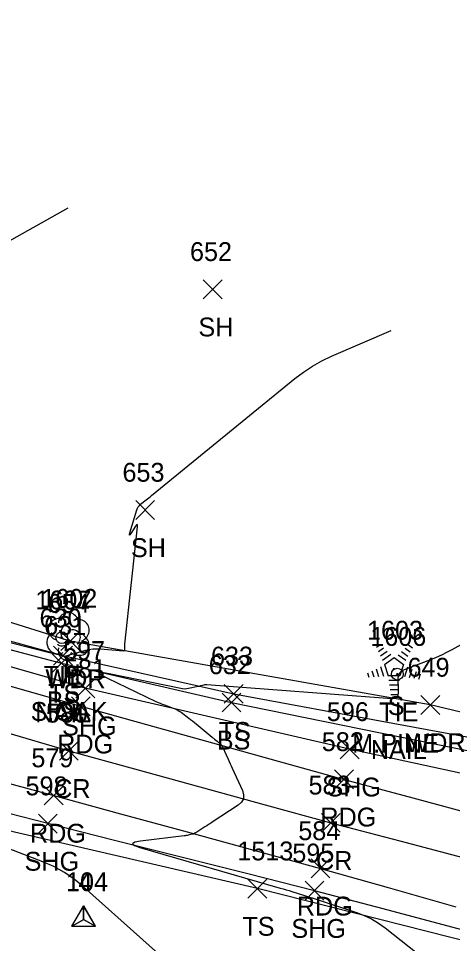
# Model space of a CAD drawing. Extents: x 1592612 to 1596497, y 111838 to 113741.
# Drawn here: x 1593074.6 to 1593120.8, y 113362.1 to 113460.3 of the extents above; entities that cross this region are included whole.
import ezdxf

# ---------------------------------------------------------------- set-up
doc = ezdxf.new("R2010")
doc.units = 0
for name, color, linetype in [('C_A', 7, 'Continuous'), ('C_C', 7, 'Continuous'), ('C_I', 7, 'Continuous'), ('CBP', 7, 'Continuous'), ('CPSM', 7, 'Continuous'), ('L_A', 7, 'Continuous'), ('L_C', 7, 'Continuous'), ('L_I', 7, 'Continuous'), ('L_TIC', 7, 'Continuous'), ('LAWA', 7, 'Continuous'), ('LELB', 7, 'Continuous'), ('LSOGCMA', 7, 'Continuous'), ('LSOGCMI', 7, 'Continuous'), ('LTC', 7, 'Continuous'), ('LTD', 7, 'Continuous'), ('P_A', 7, 'Continuous'), ('P_I', 7, 'Continuous'), ('P_TIC', 7, 'Continuous'), ('PEU', 7, 'Continuous'), ('PRC', 7, 'Continuous'), ('PSU', 7, 'Continuous')]:
    doc.layers.add(name, color=color, linetype=linetype)

msp = doc.modelspace()

# ---------------------------------------------------------------- linework, layer by layer
at = {"layer": 'CBP'}
for centre, radius in [((1593079.238, 113394.544), 0.625), ((1593079.238, 113394.544), 0.0833), ((1593114.889, 113390.674), 0.625), ((1593114.889, 113390.674), 0.0833)]:
    msp.add_circle(centre, radius, dxfattribs=at)
at = {"layer": 'CPSM'}
for p, q in [((1593080.313, 113363.916), (1593081.563, 113366.081)), ((1593080.322, 113363.912), (1593081.572, 113366.077)), ((1593082.813, 113363.916), (1593081.563, 113366.081)), ((1593081.563, 113364.637), (1593081.563, 113366.081)), ((1593082.822, 113363.912), (1593081.572, 113366.077)), ((1593081.572, 113364.633), (1593081.572, 113366.077)), ((1593080.313, 113363.916), (1593081.563, 113364.637)), ((1593080.322, 113363.912), (1593081.572, 113364.633)), ((1593081.563, 113364.637), (1593081.563, 113364.637)), ((1593081.563, 113364.637), (1593082.813, 113363.916)), ((1593081.572, 113364.633), (1593081.572, 113364.633)), ((1593081.572, 113364.633), (1593082.822, 113363.912)), ((1593080.313, 113363.916), (1593082.813, 113363.916)), ((1593080.322, 113363.912), (1593082.822, 113363.912))]:
    msp.add_line(p, q, dxfattribs=at)
at = {"layer": 'L_TIC'}
for points in [[(1593094.27, 113430.519), (1593096.27, 113432.519)], [(1593096.27, 113430.519), (1593094.27, 113432.519)], [(1593087.097, 113407.098), (1593089.097, 113409.098)], [(1593089.097, 113407.098), (1593087.097, 113409.098)], [(1593079.143, 113393.184), (1593081.143, 113395.184)], [(1593081.143, 113393.184), (1593079.143, 113395.184)], [(1593078.367, 113391.639), (1593080.367, 113393.639)], [(1593080.367, 113391.639), (1593078.367, 113393.639)], [(1593078.204, 113390.835), (1593080.204, 113392.835)], [(1593080.204, 113390.835), (1593078.204, 113392.835)], [(1593096.503, 113387.59), (1593098.503, 113389.59)], [(1593098.503, 113387.59), (1593096.503, 113389.59)], [(1593096.266, 113386.672), (1593098.266, 113388.672)], [(1593098.266, 113386.672), (1593096.266, 113388.672)], [(1593117.398, 113386.407), (1593119.398, 113388.407)], [(1593119.398, 113386.407), (1593117.398, 113388.407)], [(1593099.017, 113366.909), (1593101.017, 113368.909)], [(1593101.017, 113366.909), (1593099.017, 113368.909)]]:
    msp.add_lwpolyline(points, dxfattribs=at)
at = {"layer": 'LAWA'}
msp.add_lwpolyline([(1593169.611, 113375.165), (1593118.398, 113387.407), (1593080.143, 113394.184), (1593050.562, 113403.447), (1593019.72, 113413.06), (1592995.657, 113420.841), (1592970.681, 113431.184), (1592941.873, 113445.585), (1592917.884, 113456.286)], dxfattribs=at)
at = {"layer": 'LELB'}
for points in [[(1592908.46, 113460.258), (1592922.596, 113449.566), (1592933.267, 113441.549), (1592945.1, 113436.529), (1592970.28, 113425.515), (1592997.076, 113416.402), (1593023.641, 113407.833), (1593049.418, 113399.686), (1593079.204, 113391.835), (1593097.266, 113387.672), (1593130.658, 113380.878), (1593168.554, 113372.43)], [(1592945.373, 113437.303), (1592970.416, 113426.096), (1592997.179, 113416.812), (1593023.772, 113408.406), (1593049.589, 113400.837), (1593079.367, 113392.638), (1593097.503, 113388.59), (1593131.295, 113382.361), (1593169.279, 113374.833)], [(1593157.216, 113351.758), (1593128.266, 113360.771), (1593100.017, 113367.909), (1593070.216, 113374.835), (1593038.268, 113383.437), (1593013.967, 113383.154), (1593000.038, 113371.416), (1592985.819, 113350.727), (1592975.861, 113332.672)]]:
    msp.add_lwpolyline(points, dxfattribs=at)
at = {"layer": 'LSOGCMA'}
for points in [[(1593055.426, 113398.668), (1593078.233, 113392.909), (1593078.346, 113392.881), (1593078.459, 113392.852), (1593078.572, 113392.824), (1593078.685, 113392.796), (1593079.324, 113392.638), (1593079.344, 113392.633), (1593079.365, 113392.628), (1593079.385, 113392.623), (1593079.406, 113392.619), (1593079.524, 113392.594), (1593079.53, 113392.594), (1593079.535, 113392.594), (1593079.55, 113392.598), (1593079.555, 113392.599), (1593081.787, 113393.21), (1593082.161, 113393.295), (1593082.539, 113393.348), (1593082.92, 113393.368), (1593083.304, 113393.355), (1593085.814, 113393.165), (1593085.874, 113393.169), (1593085.916, 113393.192), (1593085.94, 113393.233), (1593085.947, 113393.292), (1593085.939, 113393.566), (1593085.938, 113393.635), (1593085.939, 113393.703), (1593085.943, 113393.771), (1593085.949, 113393.84), (1593087.285, 113406.304), (1593087.291, 113406.481), (1593087.259, 113406.552), (1593087.189, 113406.517), (1593087.082, 113406.376), (1593086.578, 113405.601), (1593086.476, 113405.459), (1593086.423, 113405.42), (1593086.418, 113405.486), (1593086.461, 113405.655), (1593087.214, 113408.122), (1593087.279, 113408.291), (1593087.368, 113408.444), (1593087.48, 113408.582), (1593087.614, 113408.703), (1593088.199, 113409.158), (1593088.345, 113409.272), (1593088.49, 113409.387), (1593088.634, 113409.503), (1593088.778, 113409.62), (1593104.007, 113422.044), (1593104.921, 113422.739), (1593105.875, 113423.366), (1593106.871, 113423.925), (1593107.908, 113424.416), (1593114.252, 113427.161)], [(1593094.835, 113356.265), (1593081.553, 113368.117), (1593080.562, 113368.925), (1593079.51, 113369.635), (1593078.399, 113370.247), (1593077.227, 113370.76), (1593071.605, 113372.928)]]:
    msp.add_lwpolyline(points, dxfattribs=at)
at = {"layer": 'LSOGCMI'}
for points in [[(1593079.878, 113440.116), (1593065.591, 113432.12)], [(1593128.624, 113397.688), (1593120.681, 113393.248), (1593120.133, 113392.954), (1593119.575, 113392.683), (1593119.007, 113392.432), (1593118.429, 113392.203), (1593115.609, 113391.145), (1593115.315, 113390.989), (1593115.107, 113390.775), (1593114.987, 113390.502), (1593114.954, 113390.17), (1593114.997, 113388.727), (1593114.961, 113388.415), (1593114.833, 113388.199), (1593114.612, 113388.081), (1593114.298, 113388.06), (1593094.648, 113389.548), (1593094.571, 113389.551), (1593094.494, 113389.547), (1593094.418, 113389.536), (1593094.343, 113389.519), (1593094.043, 113389.437), (1593093.968, 113389.417), (1593093.893, 113389.398), (1593093.817, 113389.38), (1593093.741, 113389.364), (1593092.686, 113389.14), (1593092.485, 113389.108), (1593092.284, 113389.097), (1593092.083, 113389.107), (1593091.881, 113389.138), (1593084.258, 113390.717), (1593083.489, 113390.845), (1593083.207, 113390.809), (1593083.41, 113390.609), (1593084.099, 113390.245), (1593089.249, 113387.779), (1593089.471, 113387.677), (1593089.695, 113387.58), (1593089.921, 113387.49), (1593090.151, 113387.405), (1593091.072, 113387.078), (1593091.298, 113386.989), (1593091.515, 113386.883), (1593091.724, 113386.761), (1593091.924, 113386.623), (1593092.733, 113386.019), (1593092.932, 113385.868), (1593093.129, 113385.715), (1593093.323, 113385.559), (1593093.516, 113385.4), (1593095.222, 113383.977), (1593095.285, 113383.924), (1593095.349, 113383.872), (1593095.413, 113383.82), (1593095.477, 113383.769), (1593095.757, 113383.545), (1593095.81, 113383.503), (1593095.863, 113383.459), (1593095.915, 113383.415), (1593095.966, 113383.37), (1593096.171, 113383.19), (1593096.219, 113383.143), (1593096.262, 113383.091), (1593096.299, 113383.035), (1593096.329, 113382.975), (1593096.922, 113381.652), (1593097.031, 113381.41), (1593097.139, 113381.169), (1593097.247, 113380.928), (1593097.356, 113380.687), (1593098.428, 113378.309), (1593098.561, 113377.856), (1593098.532, 113377.451), (1593098.339, 113377.093), (1593097.983, 113376.782), (1593095.215, 113374.966), (1593095.023, 113374.84), (1593094.831, 113374.715), (1593094.638, 113374.591), (1593094.445, 113374.467), (1593093.465, 113373.839), (1593093.375, 113373.786), (1593093.28, 113373.742), (1593093.182, 113373.706), (1593093.081, 113373.678), (1593092.669, 113373.584), (1593092.565, 113373.562), (1593092.461, 113373.542), (1593092.357, 113373.525), (1593092.252, 113373.511), (1593087.595, 113372.944), (1593086.983, 113372.829), (1593086.77, 113372.682), (1593086.957, 113372.503), (1593087.542, 113372.292), (1593102.454, 113367.977), (1593102.765, 113367.886), (1593103.075, 113367.794), (1593103.385, 113367.699), (1593103.694, 113367.603), (1593104.93, 113367.215), (1593105.238, 113367.117), (1593105.547, 113367.018), (1593105.855, 113366.919), (1593106.163, 113366.818), (1593110.555, 113365.373), (1593111.372, 113365.065), (1593112.152, 113364.689), (1593112.896, 113364.246), (1593113.604, 113363.735), (1593125.992, 113353.948)]]:
    msp.add_lwpolyline(points, dxfattribs=at)
at = {"layer": 'LTC'}
for p, q in [((1593112.689, 113393.542), (1593113.043, 113393.799)), ((1593112.898, 113393.076), (1593113.428, 113393.46)), ((1593116.087, 113393.782), (1593116.506, 113393.478)), ((1593113.108, 113392.61), (1593113.812, 113393.122)), ((1593113.318, 113392.145), (1593114.196, 113392.783)), ((1593114.974, 113392.737), (1593115.783, 113392.148)), ((1593115.345, 113393.085), (1593116.024, 113392.592)), ((1593115.716, 113393.434), (1593116.266, 113393.035)), ((1593113.542, 113391.69), (1593114.554, 113392.424)), ((1593113.542, 113391.69), (1593113.929, 113390.496)), ((1593114.554, 113392.424), (1593115.551, 113391.699)), ((1593115.551, 113391.699), (1593115.16, 113390.496)), ((1593111.721, 113390.821), (1593111.873, 113390.353)), ((1593112.177, 113391.038), (1593112.388, 113390.386)), ((1593112.632, 113391.254), (1593112.903, 113390.419)), ((1593113.088, 113391.47), (1593113.418, 113390.451)), ((1593115.988, 113391.428), (1593115.651, 113390.389)), ((1593116.433, 113391.178), (1593116.146, 113390.293)), ((1593116.878, 113390.928), (1593116.641, 113390.198)), ((1593117.322, 113390.678), (1593117.135, 113390.103)), ((1593115.16, 113390.496), (1593113.929, 113390.496)), ((1593115.121, 113389.996), (1593113.977, 113389.996)), ((1593115.038, 113389.496), (1593114.049, 113389.496)), ((1593114.954, 113388.996), (1593114.122, 113388.996)), ((1593114.87, 113388.496), (1593114.195, 113388.496))]:
    msp.add_line(p, q, dxfattribs=at)
at = {"layer": 'LTD'}
msp.add_line((1593079.883, 113394.715), (1593079.883, 113394.715), dxfattribs=at)
msp.add_line((1593079.883, 113394.715), (1593079.883, 113394.715), dxfattribs=at)
msp.add_arc((1593079.93, 113396.149), 1.047, 335.52715, 180.95627, dxfattribs=at)
for centre, major_axis, ratio, start_param, end_param in [((1593079.091, 113395.382), (1.21, -0.512), 0.895232, 1.570796, 4.712389), ((1593080.925, 113395.299), (-1.141, -0.483), 0.949671, 1.570796, 4.712389), ((1593079.675, 113395.173), (-0.208, -0.792), 0.645439, 3.141593, 6.283185), ((1593080.383, 113394.549), (-0.5, 0.667), 0.989748, 3.141593, 6.283185), ((1593078.8, 113394.007), (0.584, -1.042), 0.959034, 3.141593, 6.283185), ((1593080.883, 113393.882), (-1.09, 0.792), 0.841452, 1.570796, 4.712389), ((1593079.884, 113393.215), (0.265, 1.061), 0.942809, 1.570796, 4.712389), ((1593079.425, 113393.965), (-0.625, -0.083), 0.423636, 0, 3.141593)]:
    msp.add_ellipse(centre, major_axis=major_axis, ratio=ratio, start_param=start_param, end_param=end_param, dxfattribs=at)
at = {"layer": 'P_TIC'}
for points in [[(1593080.736, 113388.175), (1593082.736, 113390.175)], [(1593082.736, 113388.175), (1593080.736, 113390.175)], [(1593080.267, 113386.261), (1593082.267, 113388.261)], [(1593082.267, 113386.261), (1593080.267, 113388.261)], [(1593108.821, 113381.695), (1593110.821, 113383.695)], [(1593110.821, 113381.695), (1593108.821, 113383.695)], [(1593078.997, 113381.533), (1593080.997, 113383.533)], [(1593080.997, 113381.533), (1593078.997, 113383.533)], [(1593108.227, 113378.507), (1593110.227, 113380.507)], [(1593110.227, 113378.507), (1593108.227, 113380.507)], [(1593077.377, 113376.792), (1593079.377, 113378.792)], [(1593079.377, 113376.792), (1593077.377, 113378.792)], [(1593076.751, 113373.814), (1593078.751, 113375.814)], [(1593078.751, 113373.814), (1593076.751, 113375.814)], [(1593106.821, 113373.896), (1593108.821, 113375.896)], [(1593108.821, 113373.896), (1593106.821, 113375.896)], [(1593105.731, 113369.058), (1593107.731, 113371.058)], [(1593107.731, 113369.058), (1593105.731, 113371.058)], [(1593105.096, 113366.687), (1593107.096, 113368.687)], [(1593107.096, 113366.687), (1593105.096, 113368.687)]]:
    msp.add_lwpolyline(points, dxfattribs=at)
at = {"layer": 'PEU'}
for points in [[(1593003.018, 113410.299), (1593010.16, 113408.025), (1593017.301, 113405.751), (1593024.442, 113403.476), (1593031.659, 113401.431), (1593038.876, 113399.386), (1593046.093, 113397.341), (1593053.31, 113395.296), (1593060.299, 113393.287), (1593067.289, 113391.279), (1593074.278, 113389.27), (1593081.267, 113387.261), (1593088.257, 113385.323), (1593095.247, 113383.384), (1593102.237, 113381.446), (1593109.227, 113379.507), (1593116.551, 113377.543), (1593123.875, 113375.58)], [(1592999.818, 113401.035), (1593007.077, 113398.85), (1593014.336, 113396.666), (1593021.595, 113394.481), (1593028.817, 113392.2), (1593036.039, 113389.918), (1593043.261, 113387.637), (1593050.483, 113385.355), (1593057.456, 113383.464), (1593064.43, 113381.574), (1593071.403, 113379.683), (1593078.377, 113377.792), (1593085.465, 113375.859), (1593092.554, 113373.925), (1593099.643, 113371.992), (1593106.731, 113370.058), (1593113.913, 113368.024), (1593121.096, 113365.989)]]:
    msp.add_lwpolyline(points, dxfattribs=at)
at = {"layer": 'PRC'}
msp.add_lwpolyline([(1593001.474, 113405.968), (1593008.597, 113403.754), (1593015.719, 113401.54), (1593022.841, 113399.326), (1593030.15, 113397.192), (1593037.459, 113395.057), (1593044.767, 113392.923), (1593052.076, 113390.789), (1593059.056, 113388.725), (1593066.037, 113386.661), (1593073.017, 113384.597), (1593079.997, 113382.533), (1593086.953, 113380.624), (1593093.909, 113378.714), (1593100.865, 113376.805), (1593107.821, 113374.896), (1593115.173, 113372.97), (1593122.526, 113371.044)], dxfattribs=at)
at = {"layer": 'PSU'}
for points in [[(1593167.681, 113369.582), (1593139.7, 113376.255), (1593109.821, 113382.695), (1593081.736, 113389.175), (1593053.818, 113397.152), (1593024.821, 113405.619), (1592996.75, 113414.705), (1592967.822, 113425.179), (1592940.197, 113435.636), (1592911.843, 113443.034)], [(1593127.958, 113361.911), (1593120.671, 113363.837), (1593113.383, 113365.762), (1593106.096, 113367.687), (1593099.009, 113369.469), (1593091.923, 113371.25), (1593084.837, 113373.032), (1593077.751, 113374.814), (1593070.824, 113376.586), (1593063.897, 113378.357), (1593056.97, 113380.129), (1593050.043, 113381.901), (1593042.604, 113384.128), (1593035.164, 113386.355), (1593027.725, 113388.583), (1593020.286, 113390.81), (1593013.158, 113393.283), (1593006.031, 113395.756), (1592998.904, 113398.23)]]:
    msp.add_lwpolyline(points, dxfattribs=at)

# ---------------------------------------------------------------- texts
at = {"layer": 'C_A'}
for p in [(1593077.317, 113389.544), (1593112.968, 113385.674)]:
    msp.add_text('TIE', height=2, dxfattribs=at).set_placement(p)
at = {"layer": 'C_C'}
for p in [(1593076.42, 113385.544), (1593112.07, 113381.674)]:
    msp.add_text('NAIL', height=2, dxfattribs=at).set_placement(p)
at = {"layer": 'C_I'}
for s, p in [('1607', (1593076.42, 113397.544)), ('1606', (1593112.015, 113393.674)), ('104', (1593079.689, 113367.637)), ('4', (1593081.005, 113367.633))]:
    msp.add_text(s, height=2, dxfattribs=at).set_placement(p)
at = {"layer": 'L_A'}
for s, p in [('SH', (1593093.758, 113426.519)), ('SH', (1593086.585, 113403.098)), ('H', (1593079.316, 113389.715)), ('WDR', (1593077.505, 113389.184)), ('TS', (1593077.776, 113387.639)), ('BS', (1593077.645, 113386.835)), ('S', (1593113.88, 113386.334)), ('TS', (1593095.913, 113383.59)), ('BS', (1593095.707, 113382.672)), ('WDR', (1593115.76, 113382.407)), ('TS', (1593098.427, 113362.909))]:
    msp.add_text(s, height=2, dxfattribs=at).set_placement(p)
at = {"layer": 'L_C'}
for s, p in [('S.OAK', (1593075.93, 113385.715)), ('M.PINE', (1593110.1, 113382.334))]:
    msp.add_text(s, height=2, dxfattribs=at).set_placement(p)
at = {"layer": 'L_I'}
for s, p in [('652', (1593092.861, 113434.519)), ('653', (1593085.687, 113411.098)), ('1602', (1593077.064, 113397.715)), ('654', (1593077.733, 113397.184)), ('630', (1593076.871, 113395.639)), ('631', (1593077.361, 113394.835)), ('1603', (1593111.675, 113394.334)), ('633', (1593095.094, 113391.59)), ('632', (1593094.857, 113390.672)), ('649', (1593115.98, 113390.407)), ('1513', (1593097.891, 113370.909))]:
    msp.add_text(s, height=2, dxfattribs=at).set_placement(p)
at = {"layer": 'LTC'}
msp.add_text('.', height=1.037, rotation=270, dxfattribs=at).set_placement((1593114.436, 113391.438))
at = {"layer": 'P_A'}
for s, p in [('SHG', (1593079.272, 113384.175)), ('RDG', (1593078.755, 113382.261)), ('SHG', (1593107.356, 113377.695)), ('CR', (1593078.43, 113377.533)), ('RDG', (1593106.715, 113374.507)), ('RDG', (1593075.865, 113372.792)), ('CR', (1593106.254, 113369.896)), ('SHG', (1593075.286, 113369.814)), ('RDG', (1593104.219, 113365.058)), ('SHG', (1593103.631, 113362.687))]:
    msp.add_text(s, height=2, dxfattribs=at).set_placement(p)
at = {"layer": 'P_I'}
for s, p in [('597', (1593079.374, 113392.175)), ('581', (1593079.472, 113390.261)), ('596', (1593107.404, 113385.695)), ('580', (1593077.548, 113385.533)), ('582', (1593106.865, 113382.507)), ('579', (1593076.007, 113380.792)), ('598', (1593075.388, 113377.814)), ('583', (1593105.458, 113377.896)), ('584', (1593104.369, 113373.058)), ('595', (1593103.733, 113370.687))]:
    msp.add_text(s, height=2, dxfattribs=at).set_placement(p)

doc.saveas('drawing.dxf')
